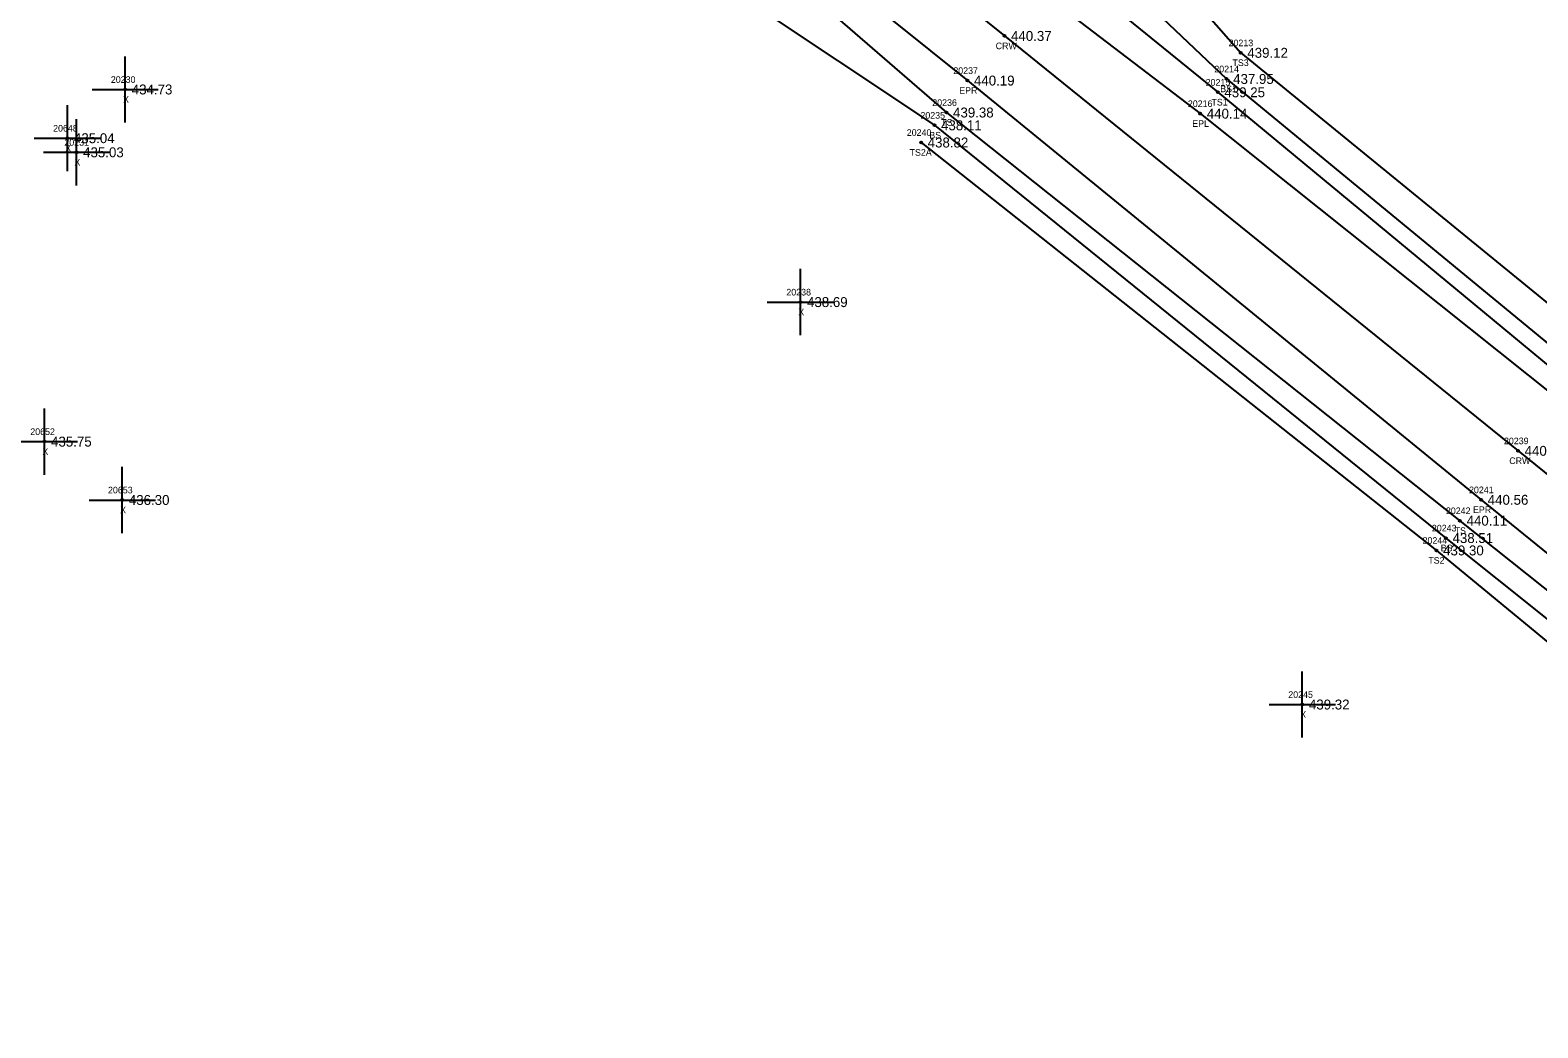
# Model space of a CAD drawing. Extents: x 1613836 to 1615109, y 777151 to 778248.
# Drawn here: x 1614452.4 to 1614680.1, y 777434.8 to 777585.5 of the extents above; entities that cross this region are included whole.
import ezdxf

# ---------------------------------------------------------------- set-up
doc = ezdxf.new("R2010")
doc.units = 0
for name, color, linetype in [('RD_DTM_BkLn1', 7, 'Continuous'), ('RD_DTM_BkLn2', 7, 'Continuous'), ('RD_DTM_BkLn_txCode', 7, 'Continuous'), ('RD_EX_Misc', 7, 'Continuous'), ('RD_EX_Misc_txCode', 7, 'Continuous'), ('RD_EX_Road', 7, 'Continuous'), ('RD_EX_Road_txCode', 7, 'Continuous'), ('RD_EX_TX_Misc_ELEV', 7, 'Continuous'), ('RD_EX_TX_Road_ELEV', 7, 'Continuous'), ('RD_HC_Survey_ELEV', 7, 'Continuous'), ('RD_HC_Survey_txCode', 7, 'Continuous'), ('RD_SMD_Locator', 7, 'Continuous')]:
    doc.layers.add(name, color=color, linetype=linetype)

msp = doc.modelspace()

# ---------------------------------------------------------------- linework, layer by layer
at = {"layer": 'RD_DTM_BkLn1'}
msp.add_lwpolyline([(1614479.01, 777681.63), (1614521.59, 777647.42), (1614599.56, 777584.67), (1614677.14, 777521.99), (1614754.7, 777459.32), (1614832.45, 777396.45), (1614909.52, 777332.99), (1614951.1, 777299.39), (1614987.2, 777270.31), (1615065.15, 777207.54)], dxfattribs=at)
at = {"layer": 'RD_DTM_BkLn2'}
for points in [[(1614480.98, 777699.79), (1614497.59, 777703), (1614522.19, 777696.07), (1614543.87, 777680.98), (1614547.65, 777678.09), (1614587.23, 777635.96), (1614610.74, 777599.44), (1614633.11, 777578.17), (1614686.46, 777534.25), (1614763.32, 777471.34), (1614841.29, 777408.4), (1614909.19, 777352.07)], [(1614487.8, 777694.98), (1614468.11, 777671.48), (1614470.95, 777667.94), (1614510.68, 777634.64), (1614563.11, 777597.11), (1614590.8, 777573.1), (1614668.37, 777511.43), (1614746.83, 777448.93), (1614824, 777386.05), (1614902.11, 777323.38), (1614943.6, 777288.77), (1614978.33, 777258.85), (1615057.35, 777197.32)], [(1614487.8, 777694.98), (1614492.09, 777693.24), (1614539.12, 777670.15), (1614581.25, 777629.02), (1614608.07, 777595.47), (1614631.79, 777576.16), (1614684.94, 777532.19), (1614761.79, 777469.29), (1614840.42, 777406.78), (1614908.46, 777350.38), (1614912.05, 777350.16), (1614911.85, 777355.47)], [(1614459.93, 777668.19), (1614463.78, 777659.09), (1614488.02, 777636.81), (1614504.08, 777625.83), (1614559.77, 777590.67), (1614588.99, 777571.17), (1614666.25, 777508.81), (1614744.8, 777446.03), (1614822.12, 777383.78), (1614899.86, 777320.65), (1614938.98, 777288.55), (1614940.53, 777287.22)], [(1614614.42, 777605.82), (1614635.25, 777582.12), (1614690.07, 777537.42), (1614767.2, 777474.86), (1614846.75, 777413.92), (1614911.85, 777355.47)], [(1614586.97, 777568.57), (1614664.83, 777506.94), (1614742.31, 777443.08), (1614819.3, 777379.66), (1614897.91, 777318.71), (1614936.23, 777288.24)]]:
    msp.add_lwpolyline(points, dxfattribs=at)
at = {"layer": 'RD_EX_Misc'}
for p, q in [((1614466.74, 777571.58), (1614466.74, 777581.58)), ((1614461.74, 777576.58), (1614471.74, 777576.58)), ((1614458.01, 777564.22), (1614458.01, 777574.22)), ((1614459.39, 777562.09), (1614459.39, 777572.09)), ((1614453.01, 777569.22), (1614463.01, 777569.22)), ((1614454.39, 777567.09), (1614464.39, 777567.09)), ((1614568.74, 777539.46), (1614568.74, 777549.46)), ((1614563.74, 777544.46), (1614573.74, 777544.46)), ((1614454.55, 777518.38), (1614454.55, 777528.38)), ((1614449.55, 777523.38), (1614459.55, 777523.38)), ((1614466.3, 777509.56), (1614466.3, 777519.56)), ((1614461.3, 777514.56), (1614471.3, 777514.56)), ((1614644.56, 777478.66), (1614644.56, 777488.66)), ((1614639.56, 777483.66), (1614649.56, 777483.66))]:
    msp.add_line(p, q, dxfattribs=at)
at = {"layer": 'RD_EX_Road'}
for points in [[(1614484.15, 777687.93), (1614479.01, 777681.63), (1614474.14, 777675.5), (1614516.4, 777641.23), (1614565.54, 777600.82), (1614593.96, 777577.93), (1614671.57, 777514.59), (1614748.82, 777451.94), (1614826.23, 777388.93), (1614903.92, 777325.97), (1614945.38, 777292), (1614981.73, 777262.81), (1615059.73, 777200.12)], [(1614484.15, 777687.93), (1614527.25, 777653.67), (1614604.97, 777591.41), (1614629.13, 777572.93), (1614683.14, 777529.85), (1614759.91, 777466.85), (1614838.21, 777403.78), (1614915.19, 777340.18), (1614934.98, 777324.5), (1615070.79, 777214.66)]]:
    msp.add_lwpolyline(points, dxfattribs=at)
at = {"layer": 'RD_SMD_Locator'}
for centre in [(1614599.56, 777584.67), (1614635.25, 777582.12), (1614593.96, 777577.93), (1614633.11, 777578.17), (1614466.74, 777576.58), (1614631.79, 777576.16), (1614590.8, 777573.1), (1614629.13, 777572.93), (1614588.99, 777571.17), (1614458.01, 777569.22), (1614586.97, 777568.57), (1614459.39, 777567.09), (1614568.74, 777544.46), (1614454.55, 777523.38), (1614677.14, 777521.99), (1614466.3, 777514.56), (1614671.57, 777514.59), (1614668.37, 777511.43), (1614666.25, 777508.81), (1614664.83, 777506.94), (1614644.56, 777483.66)]:
    msp.add_circle(centre, 0.15, dxfattribs=at)

# ---------------------------------------------------------------- texts
at = {"layer": 'RD_DTM_BkLn_txCode'}
for s, p in [('20213', (1614633.42, 777583.12)), ('20214', (1614631.27, 777579.17)), ('TS3', (1614634.01, 777580.12)), ('20215', (1614629.96, 777577.16)), ('BS1', (1614632.16, 777576.17)), ('20236', (1614588.66, 777574.1)), ('TS1', (1614630.83, 777574.16)), ('20235', (1614586.87, 777572.17)), ('20240', (1614584.81, 777569.57)), ('BS', (1614588.21, 777569.17)), ('TS', (1614590.01, 777571.1)), ('TS2A', (1614585.23, 777566.57)), ('20242', (1614666.25, 777512.43)), ('20243', (1614664.13, 777509.81)), ('20244', (1614662.72, 777507.94)), ('TS', (1614667.57, 777509.43)), ('BS', (1614665.47, 777506.81)), ('TS2', (1614663.59, 777504.94))]:
    msp.add_text(s, height=1, dxfattribs=at).set_placement(p)
at = {"layer": 'RD_EX_Misc_txCode'}
for s, p in [('20230', (1614464.58, 777577.58)), ('X', (1614466.42, 777574.58)), ('20648', (1614455.86, 777570.22)), ('20231', (1614457.56, 777568.09)), ('X', (1614457.69, 777567.22)), ('X', (1614459.08, 777565.09)), ('20238', (1614566.62, 777545.46)), ('X', (1614568.42, 777542.46)), ('20652', (1614452.41, 777524.38)), ('X', (1614454.24, 777521.38)), ('20653', (1614464.15, 777515.56)), ('X', (1614465.98, 777512.56)), ('20245', (1614642.44, 777484.66)), ('X', (1614644.25, 777481.66))]:
    msp.add_text(s, height=1, dxfattribs=at).set_placement(p)
at = {"layer": 'RD_EX_Road_txCode'}
for s, p in [('20237', (1614591.84, 777578.93)), ('EPR', (1614592.73, 777575.93)), ('20216', (1614627.27, 777573.93)), ('EPL', (1614627.93, 777570.93)), ('20241', (1614669.74, 777515.59)), ('EPR', (1614670.34, 777512.59))]:
    msp.add_text(s, height=1, dxfattribs=at).set_placement(p)
at = {"layer": 'RD_EX_TX_Misc_ELEV'}
for s, p in [('439.12', (1614636.25, 777581.37)), ('434.73', (1614467.74, 777575.83)), ('439.25', (1614632.79, 777575.41)), ('437.95', (1614634.11, 777577.42)), ('439.38', (1614591.8, 777572.35)), ('435.04', (1614459.01, 777568.47)), ('438.11', (1614589.99, 777570.42)), ('435.03', (1614460.39, 777566.34)), ('438.82', (1614587.97, 777567.82)), ('438.69', (1614569.74, 777543.71)), ('435.75', (1614455.55, 777522.63)), ('436.30', (1614467.3, 777513.81)), ('440.11', (1614669.37, 777510.68)), ('438.51', (1614667.25, 777508.06)), ('439.30', (1614665.83, 777506.19)), ('439.32', (1614645.56, 777482.91))]:
    msp.add_text(s, height=1.5, dxfattribs=at).set_placement(p)
at = {"layer": 'RD_EX_TX_Road_ELEV'}
for s, p in [('440.19', (1614594.96, 777577.18)), ('440.14', (1614630.13, 777572.18)), ('440.56', (1614672.57, 777513.84))]:
    msp.add_text(s, height=1.5, dxfattribs=at).set_placement(p)
at = {"layer": 'RD_HC_Survey_ELEV'}
for s, p in [('440.37', (1614600.56, 777583.92)), ('440.64', (1614678.14, 777521.24))]:
    msp.add_text(s, height=1.5, dxfattribs=at).set_placement(p)
at = {"layer": 'RD_HC_Survey_txCode'}
for s, p in [('CRW', (1614598.24, 777582.67)), ('20239', (1614675.02, 777522.99)), ('CRW', (1614675.82, 777519.99))]:
    msp.add_text(s, height=1, dxfattribs=at).set_placement(p)

doc.saveas('drawing.dxf')
